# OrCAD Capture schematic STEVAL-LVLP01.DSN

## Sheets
1 01_Gate_Driver: size A4; title: B-DRIVE-LPLV01; rev: 1.0; company: STMicroelectronics; note: N/A; note: AMG ANALOG
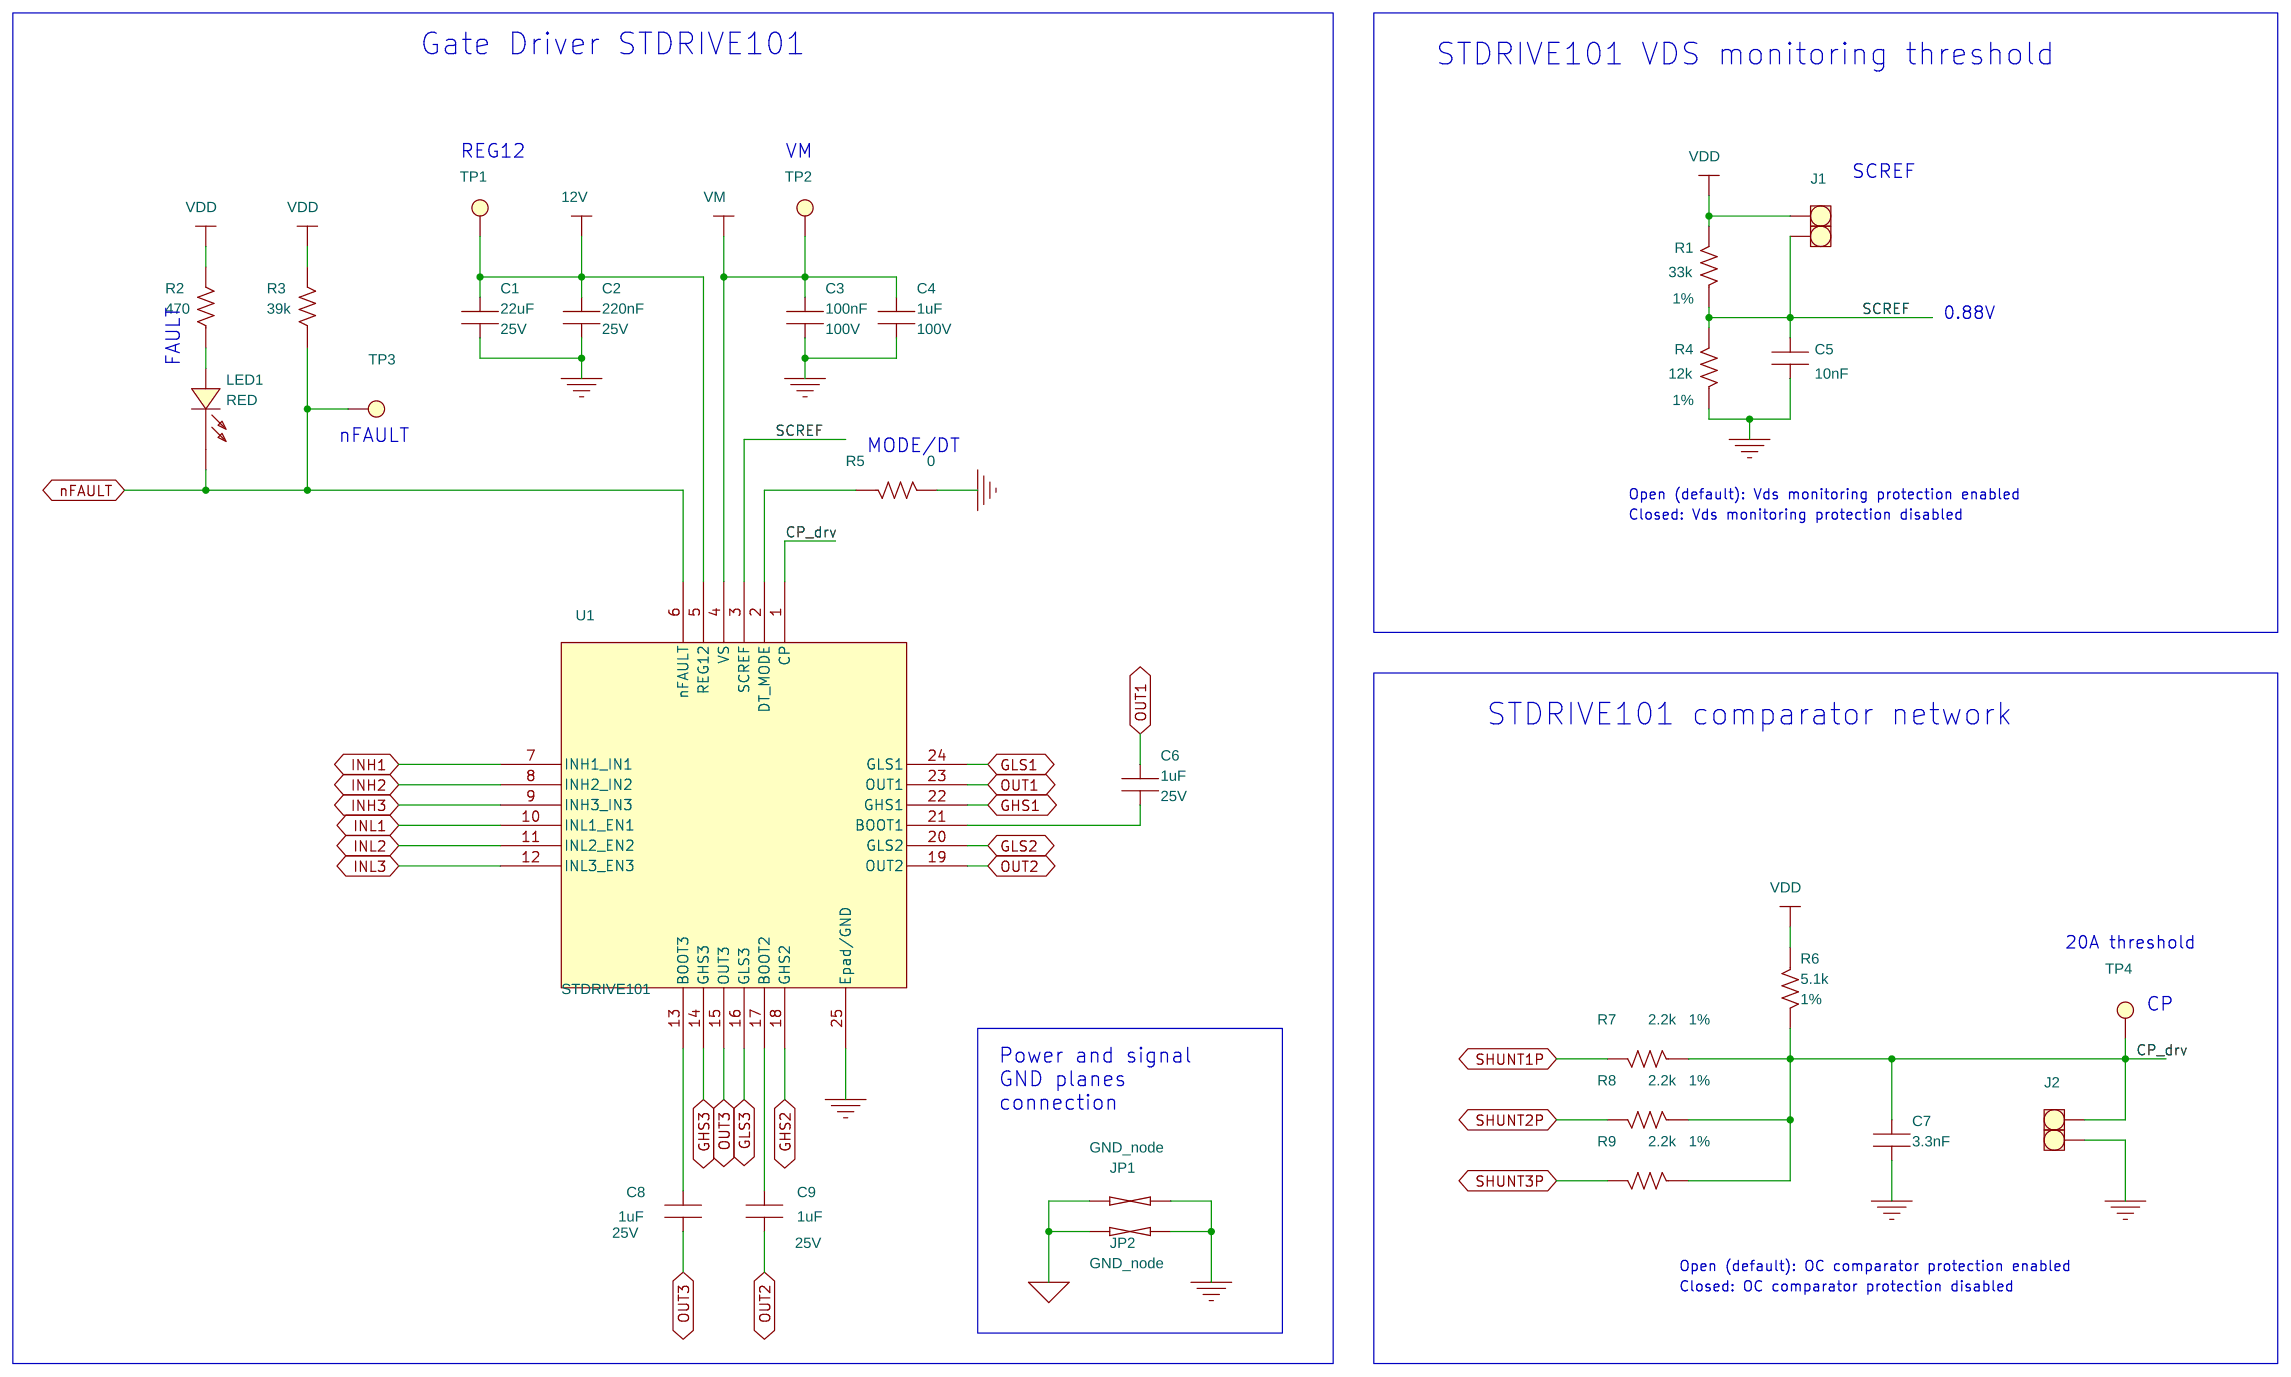
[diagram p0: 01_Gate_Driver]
2 02_Power_stage: size A4
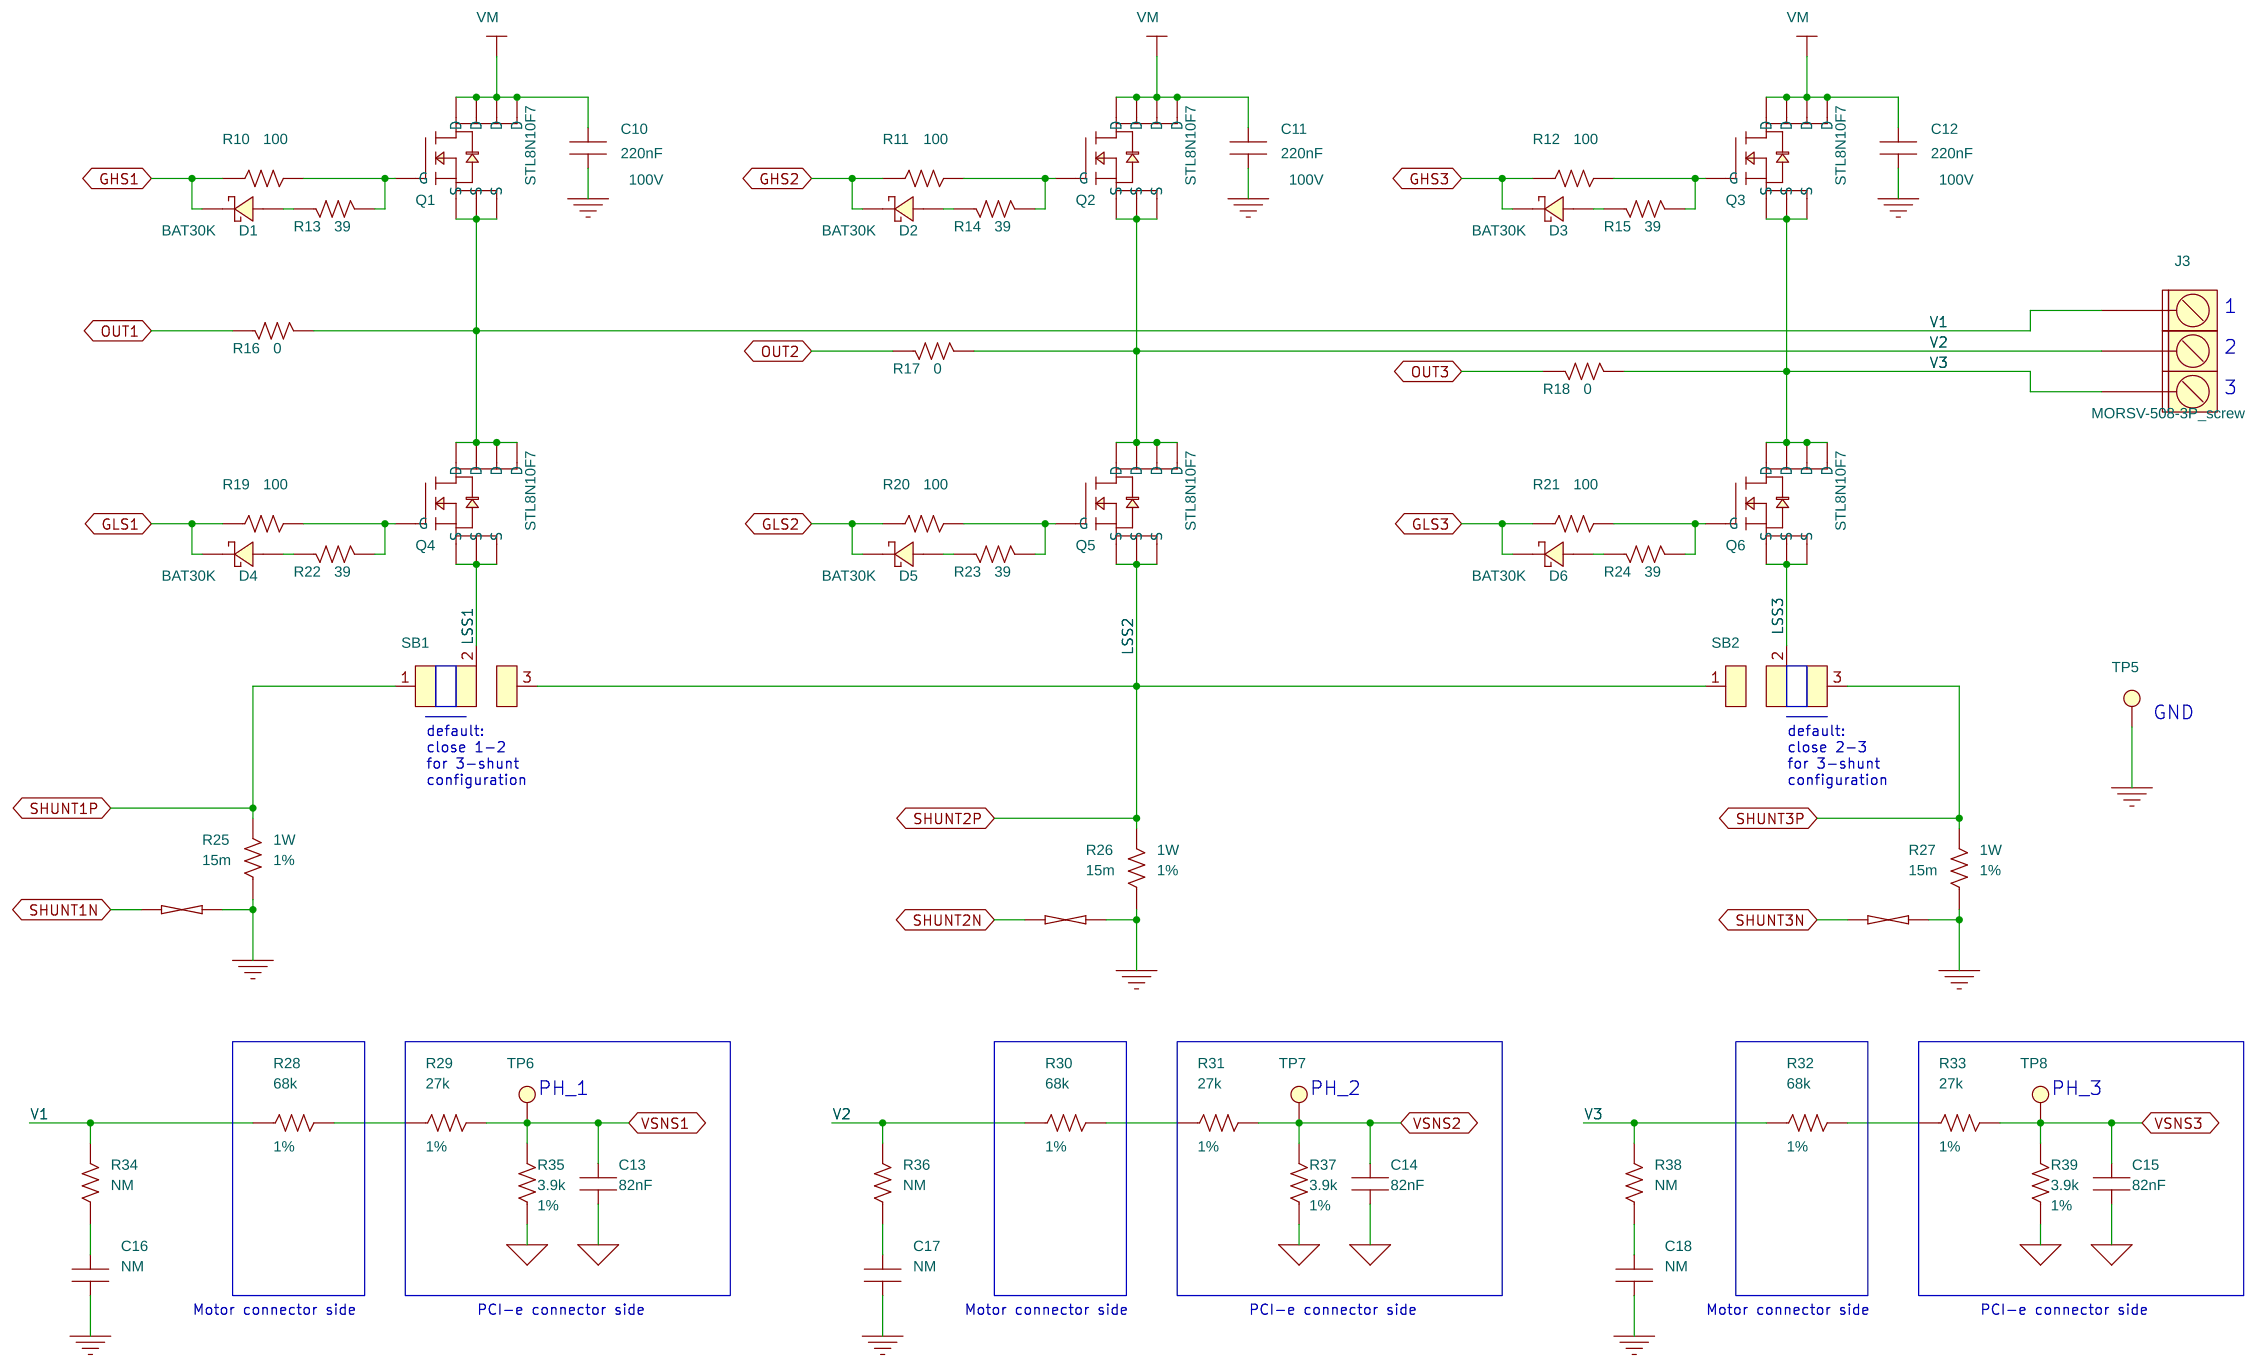
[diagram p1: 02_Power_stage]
3 03_Current_sens: size A4
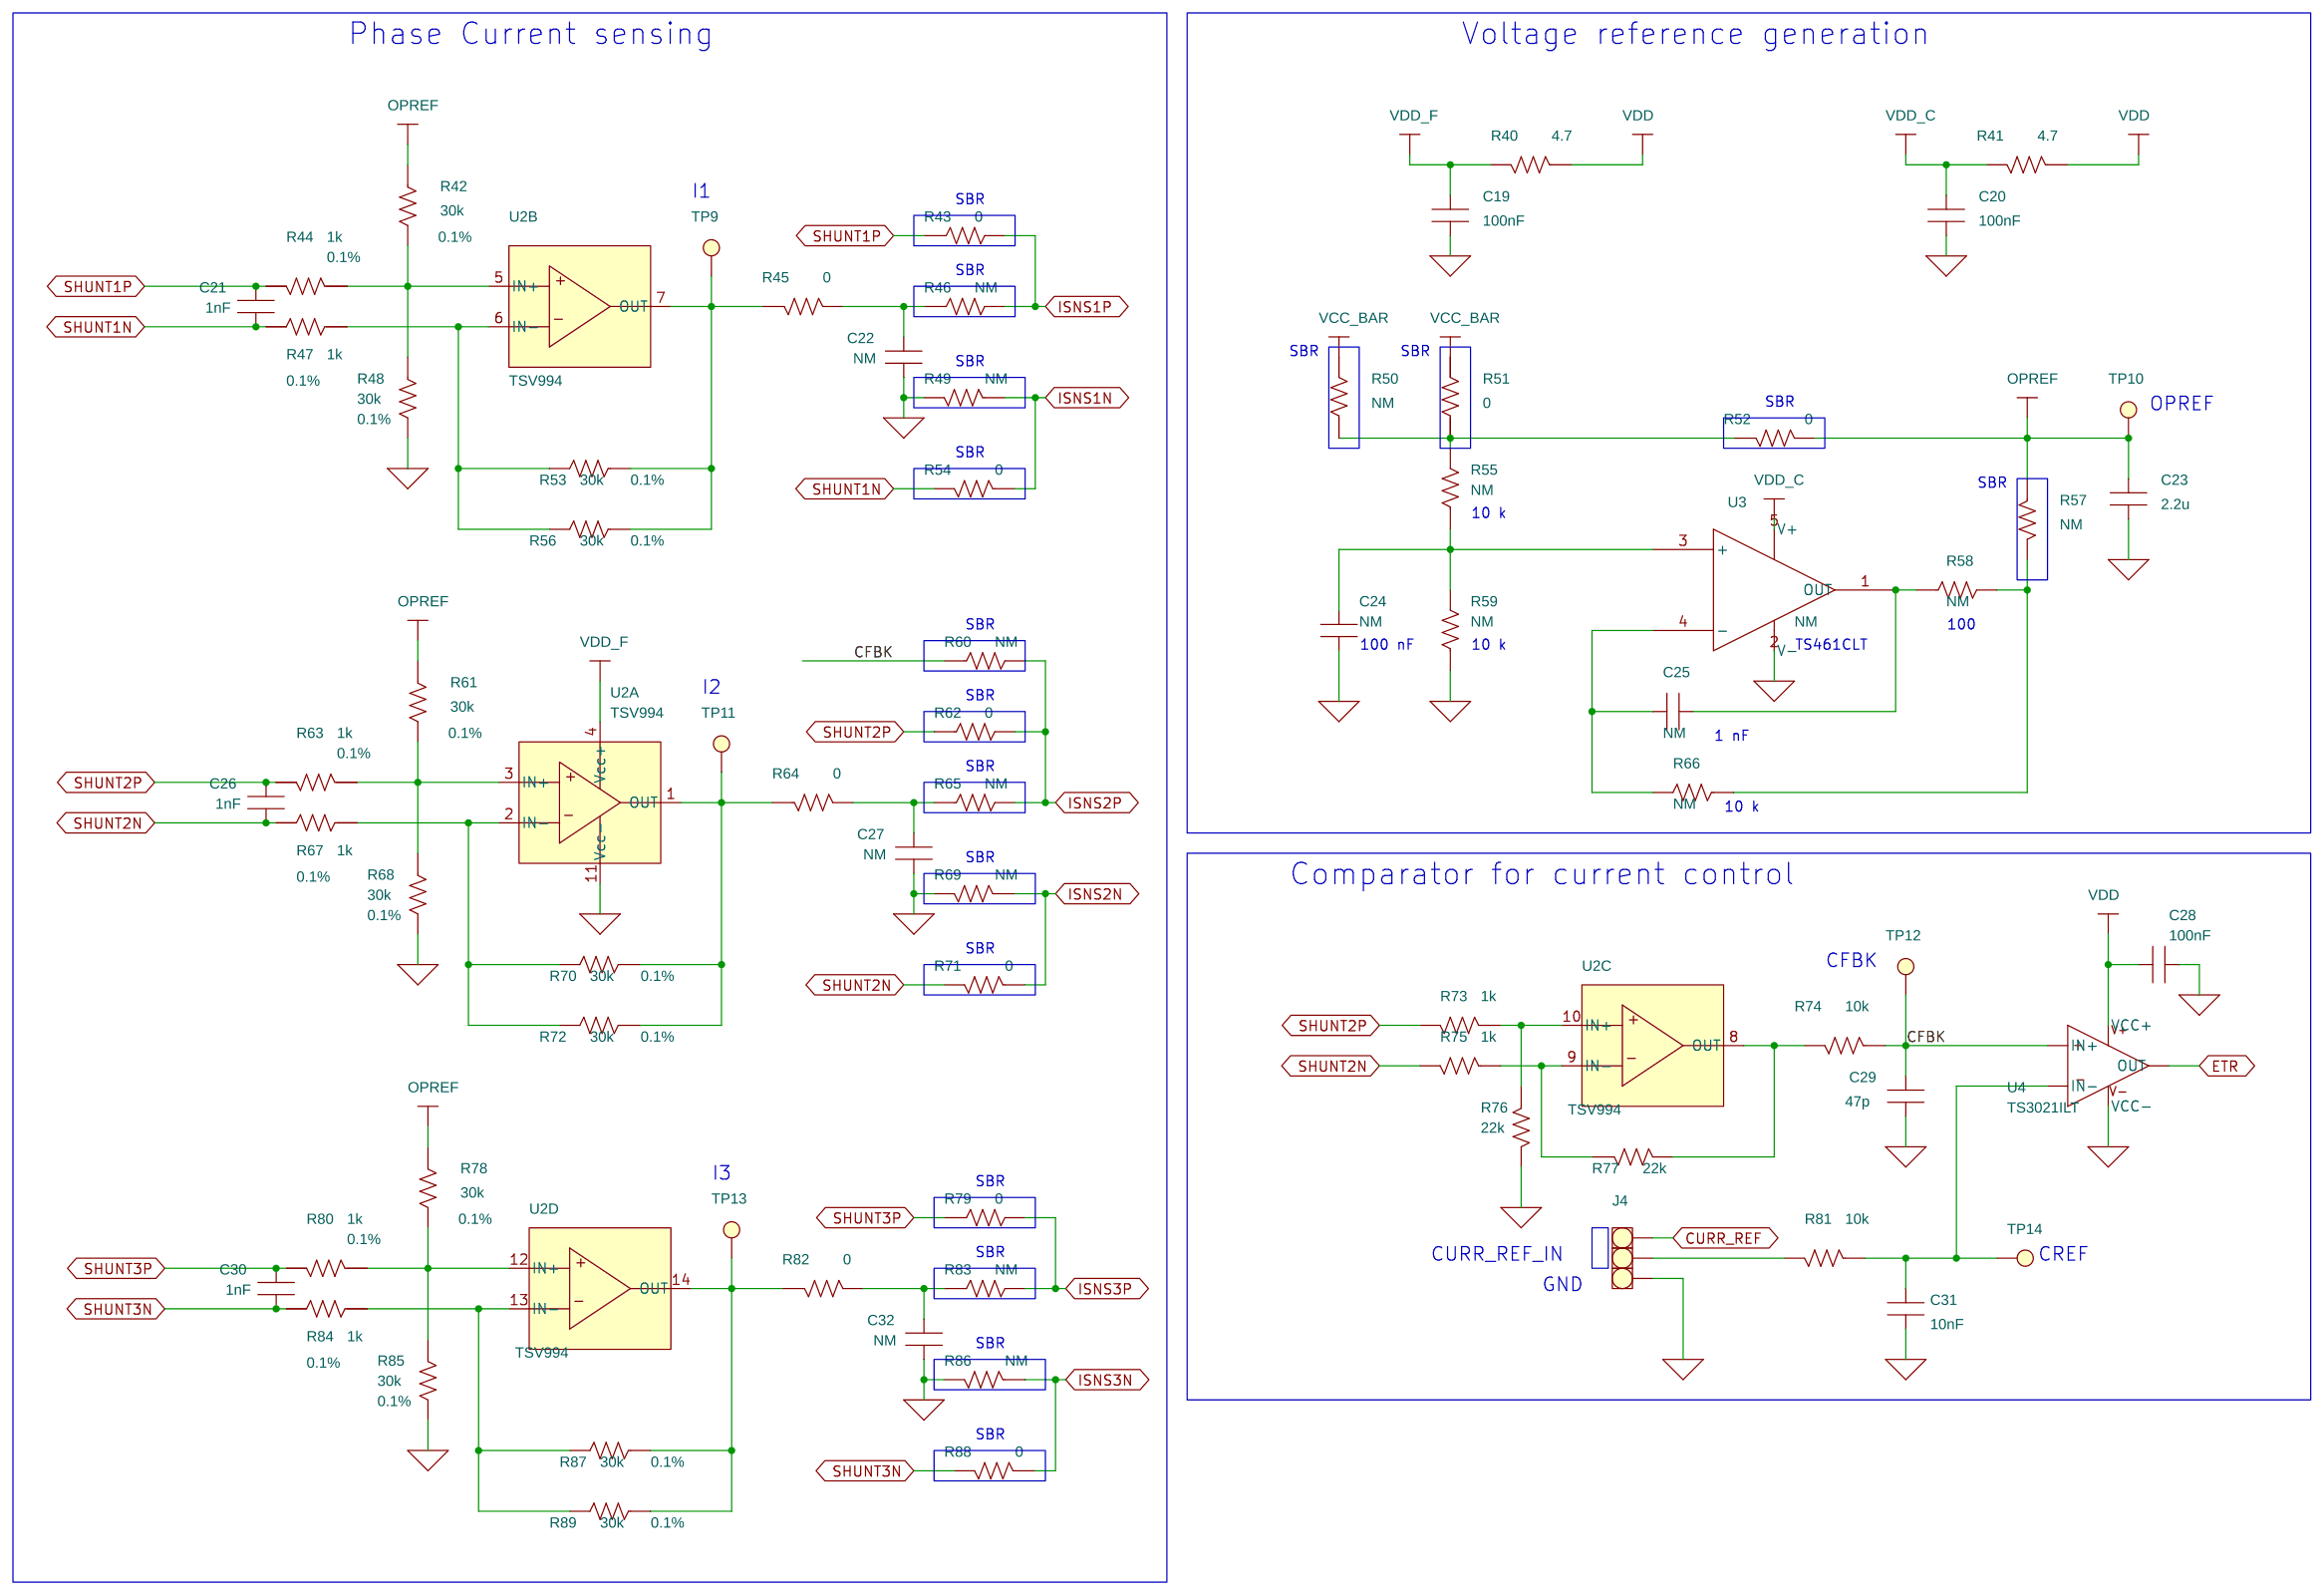
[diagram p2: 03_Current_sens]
4 04_Buck_Converter: size A4
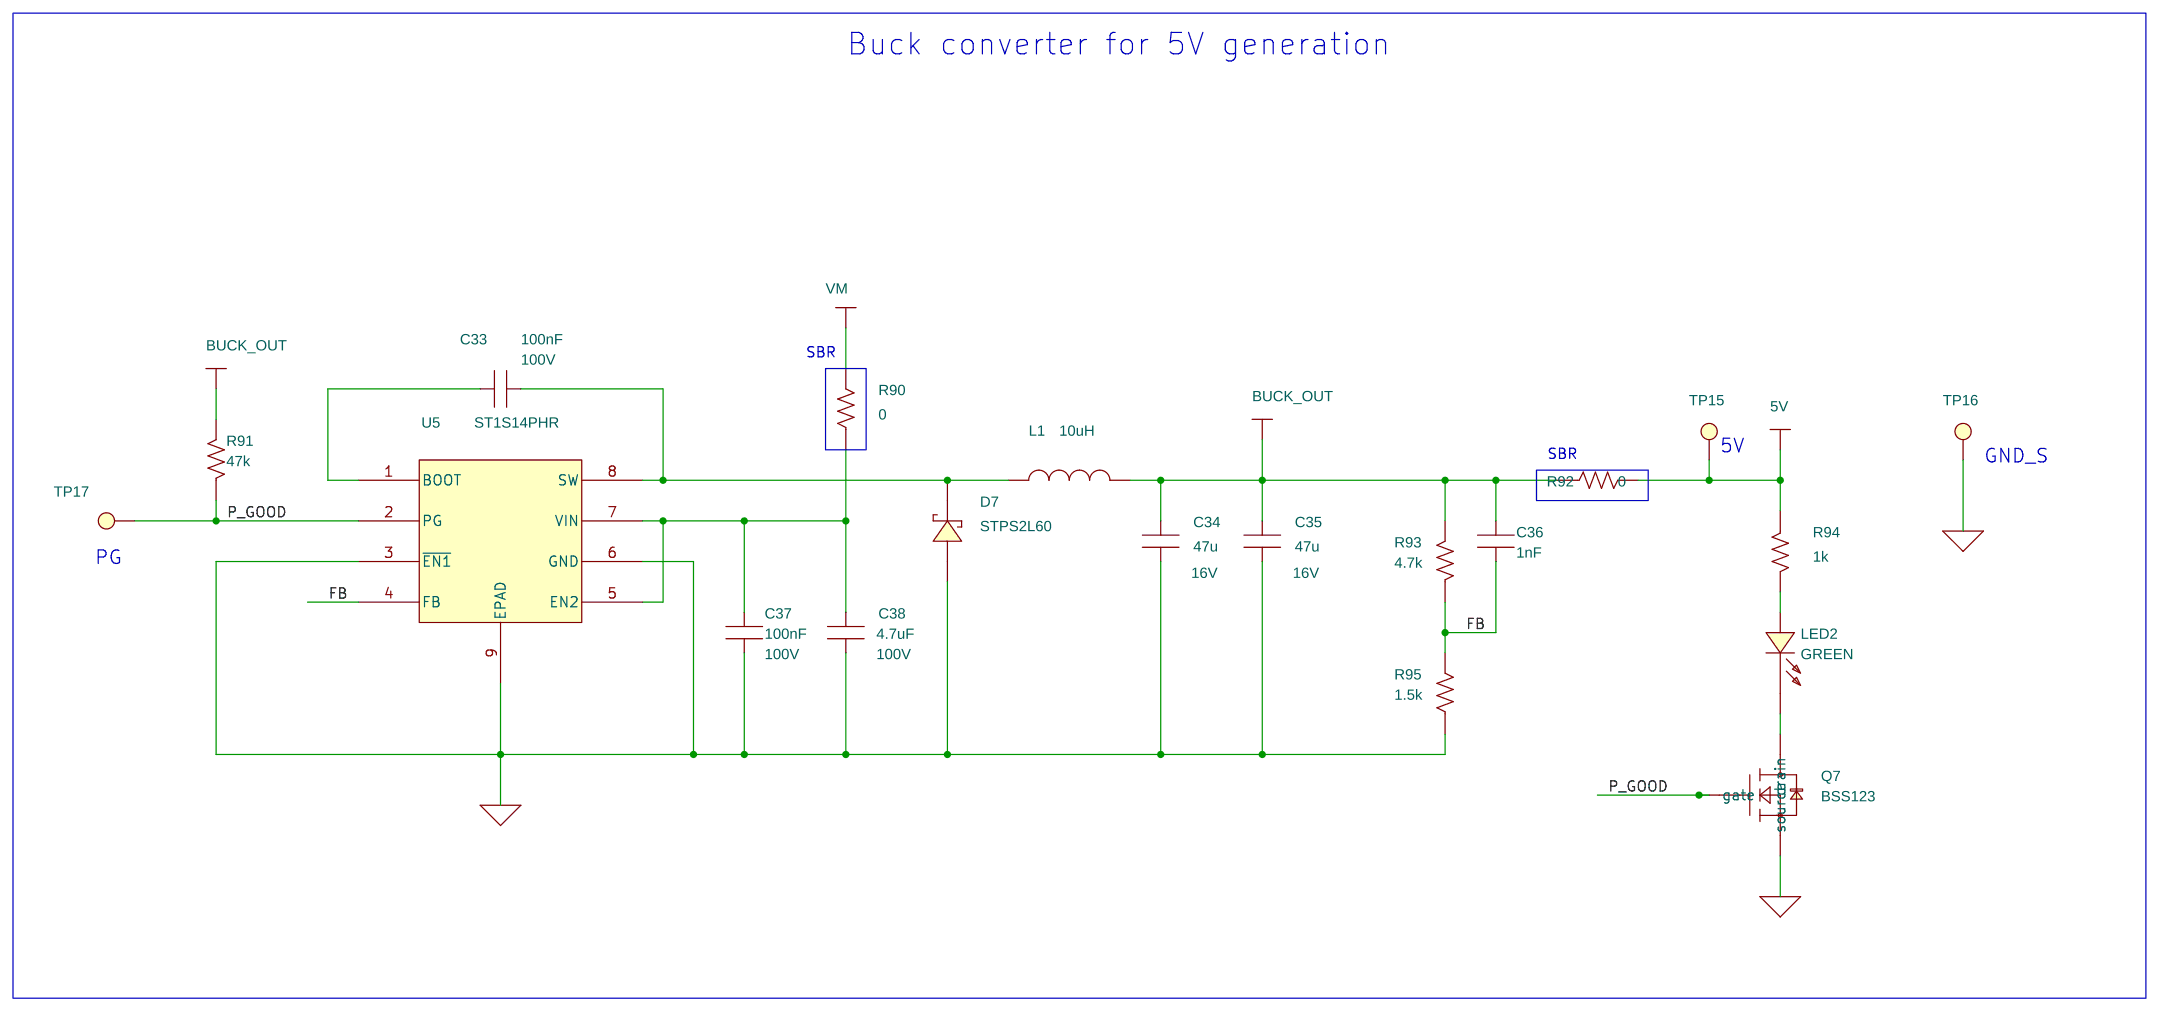
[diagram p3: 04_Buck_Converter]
5 05_Misc_Connectors: size A4
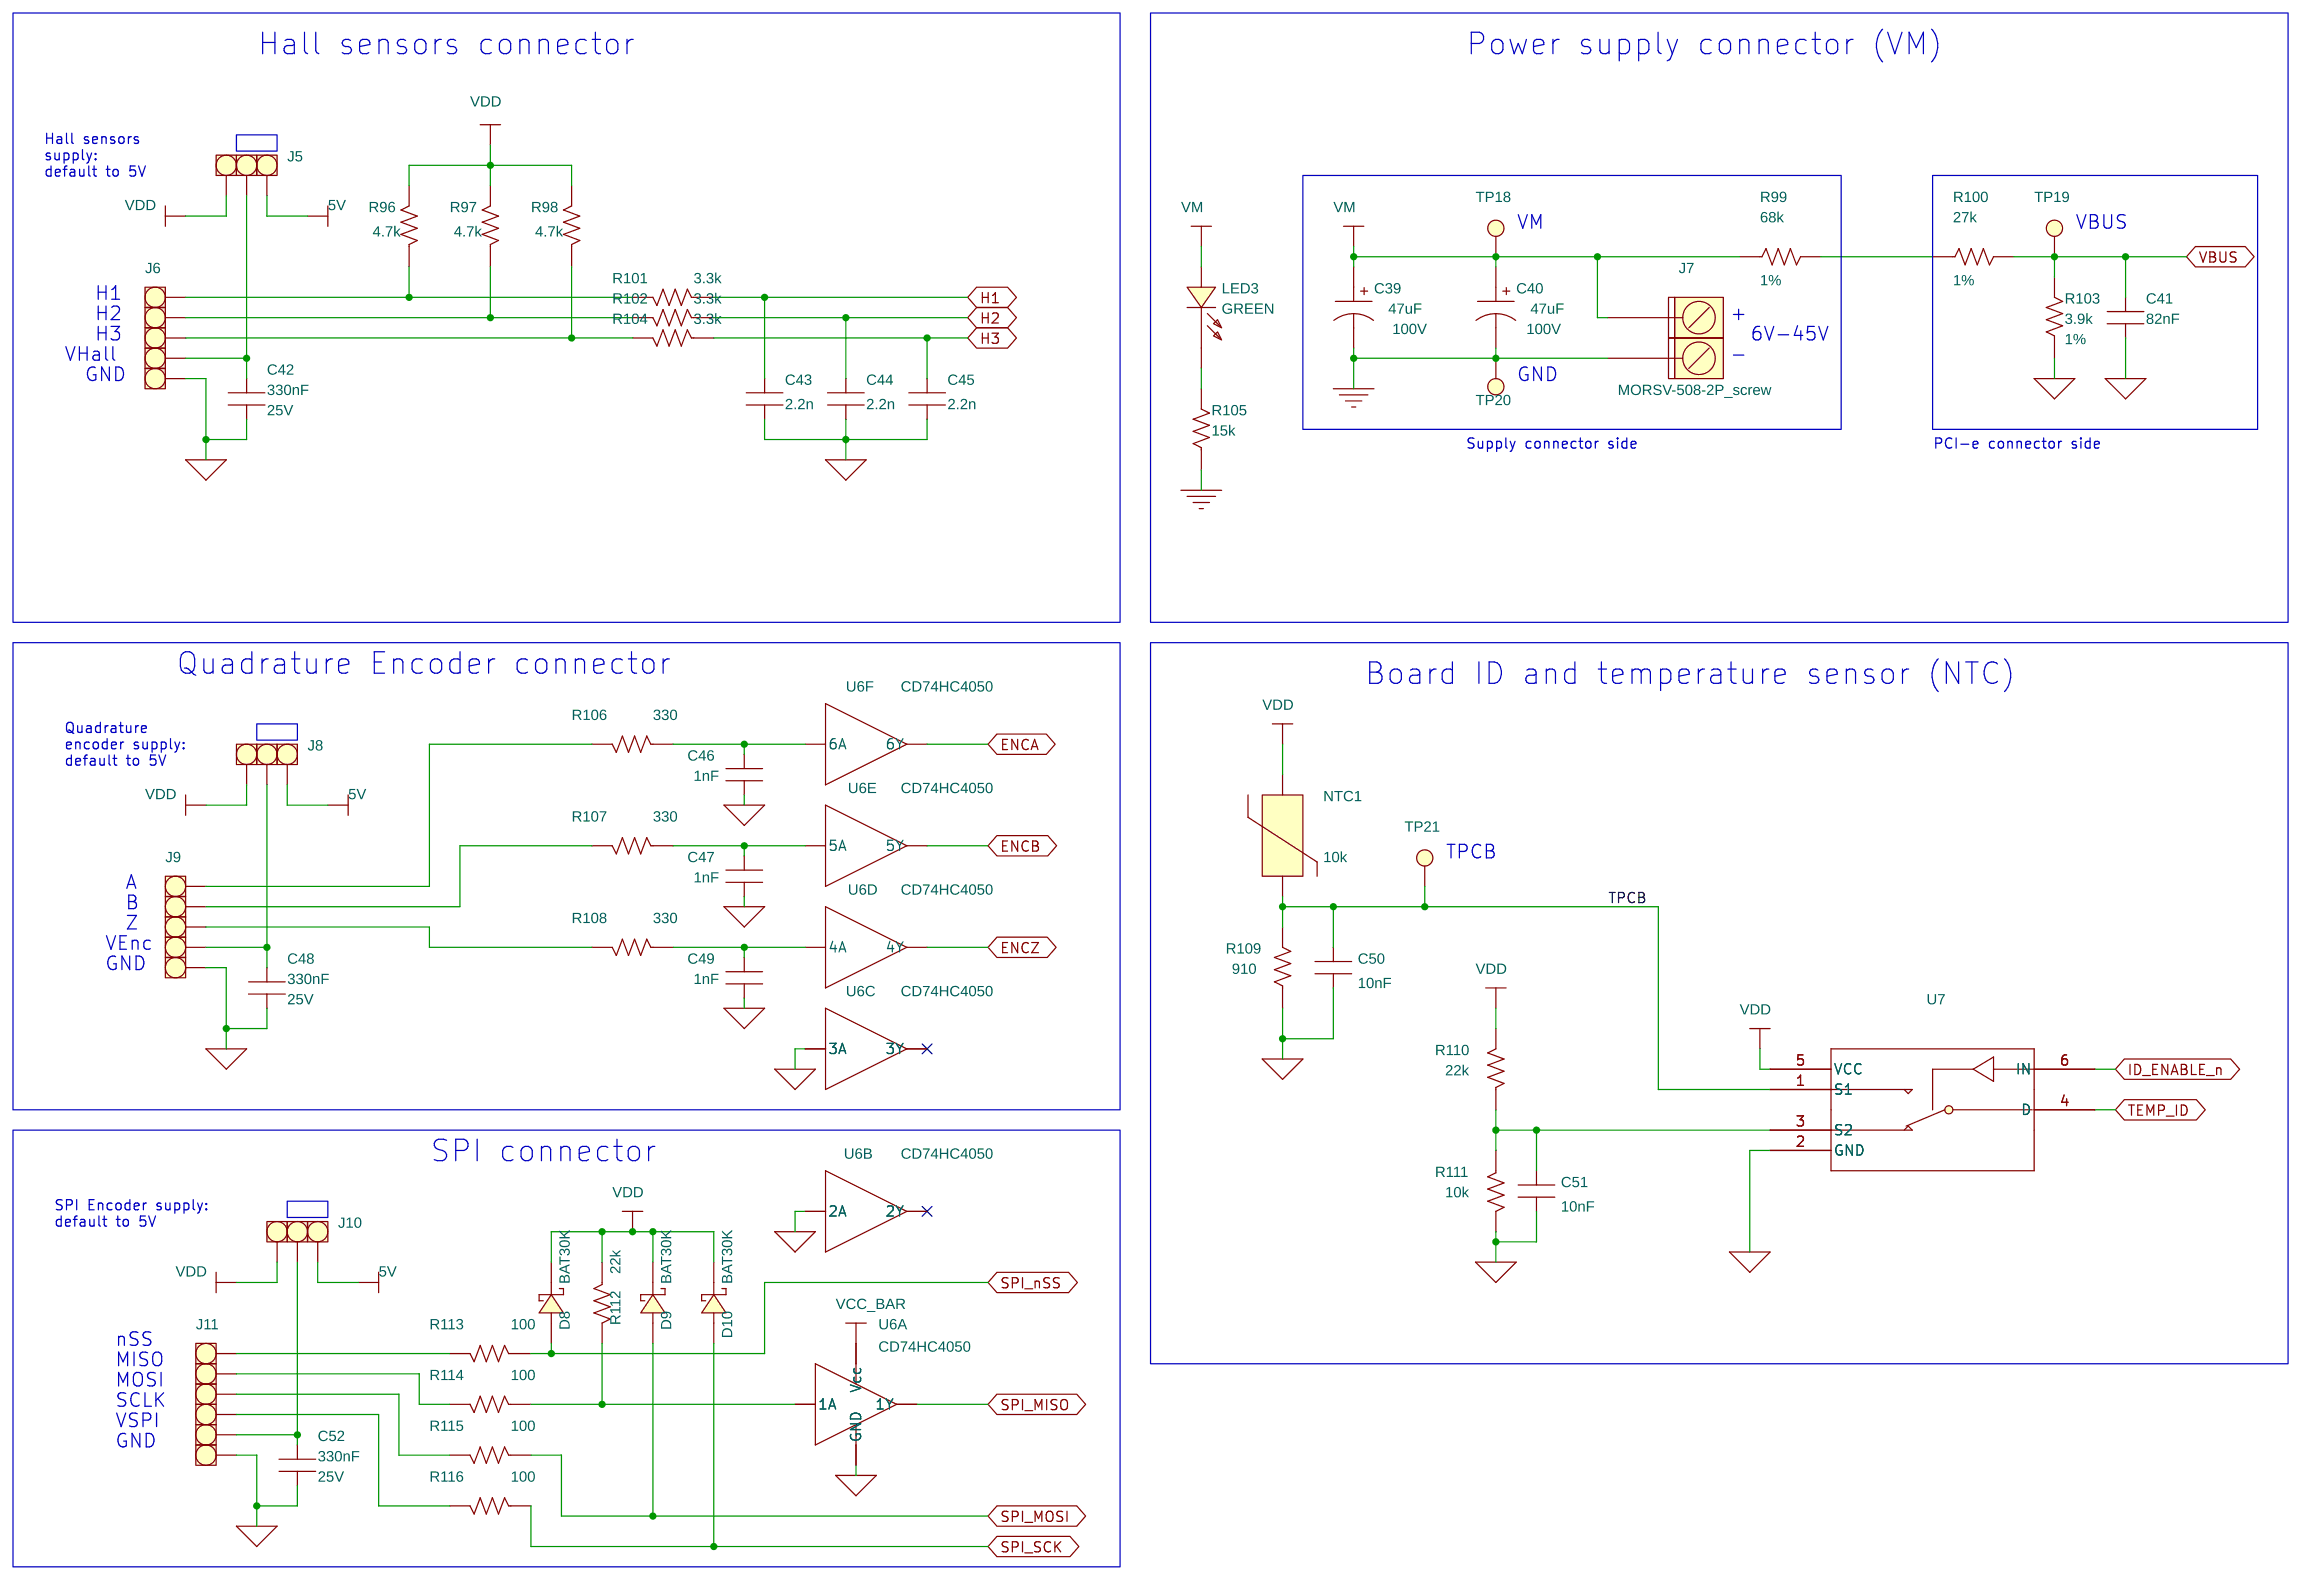
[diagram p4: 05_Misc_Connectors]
6 06_MC_Connector_V2: size A4
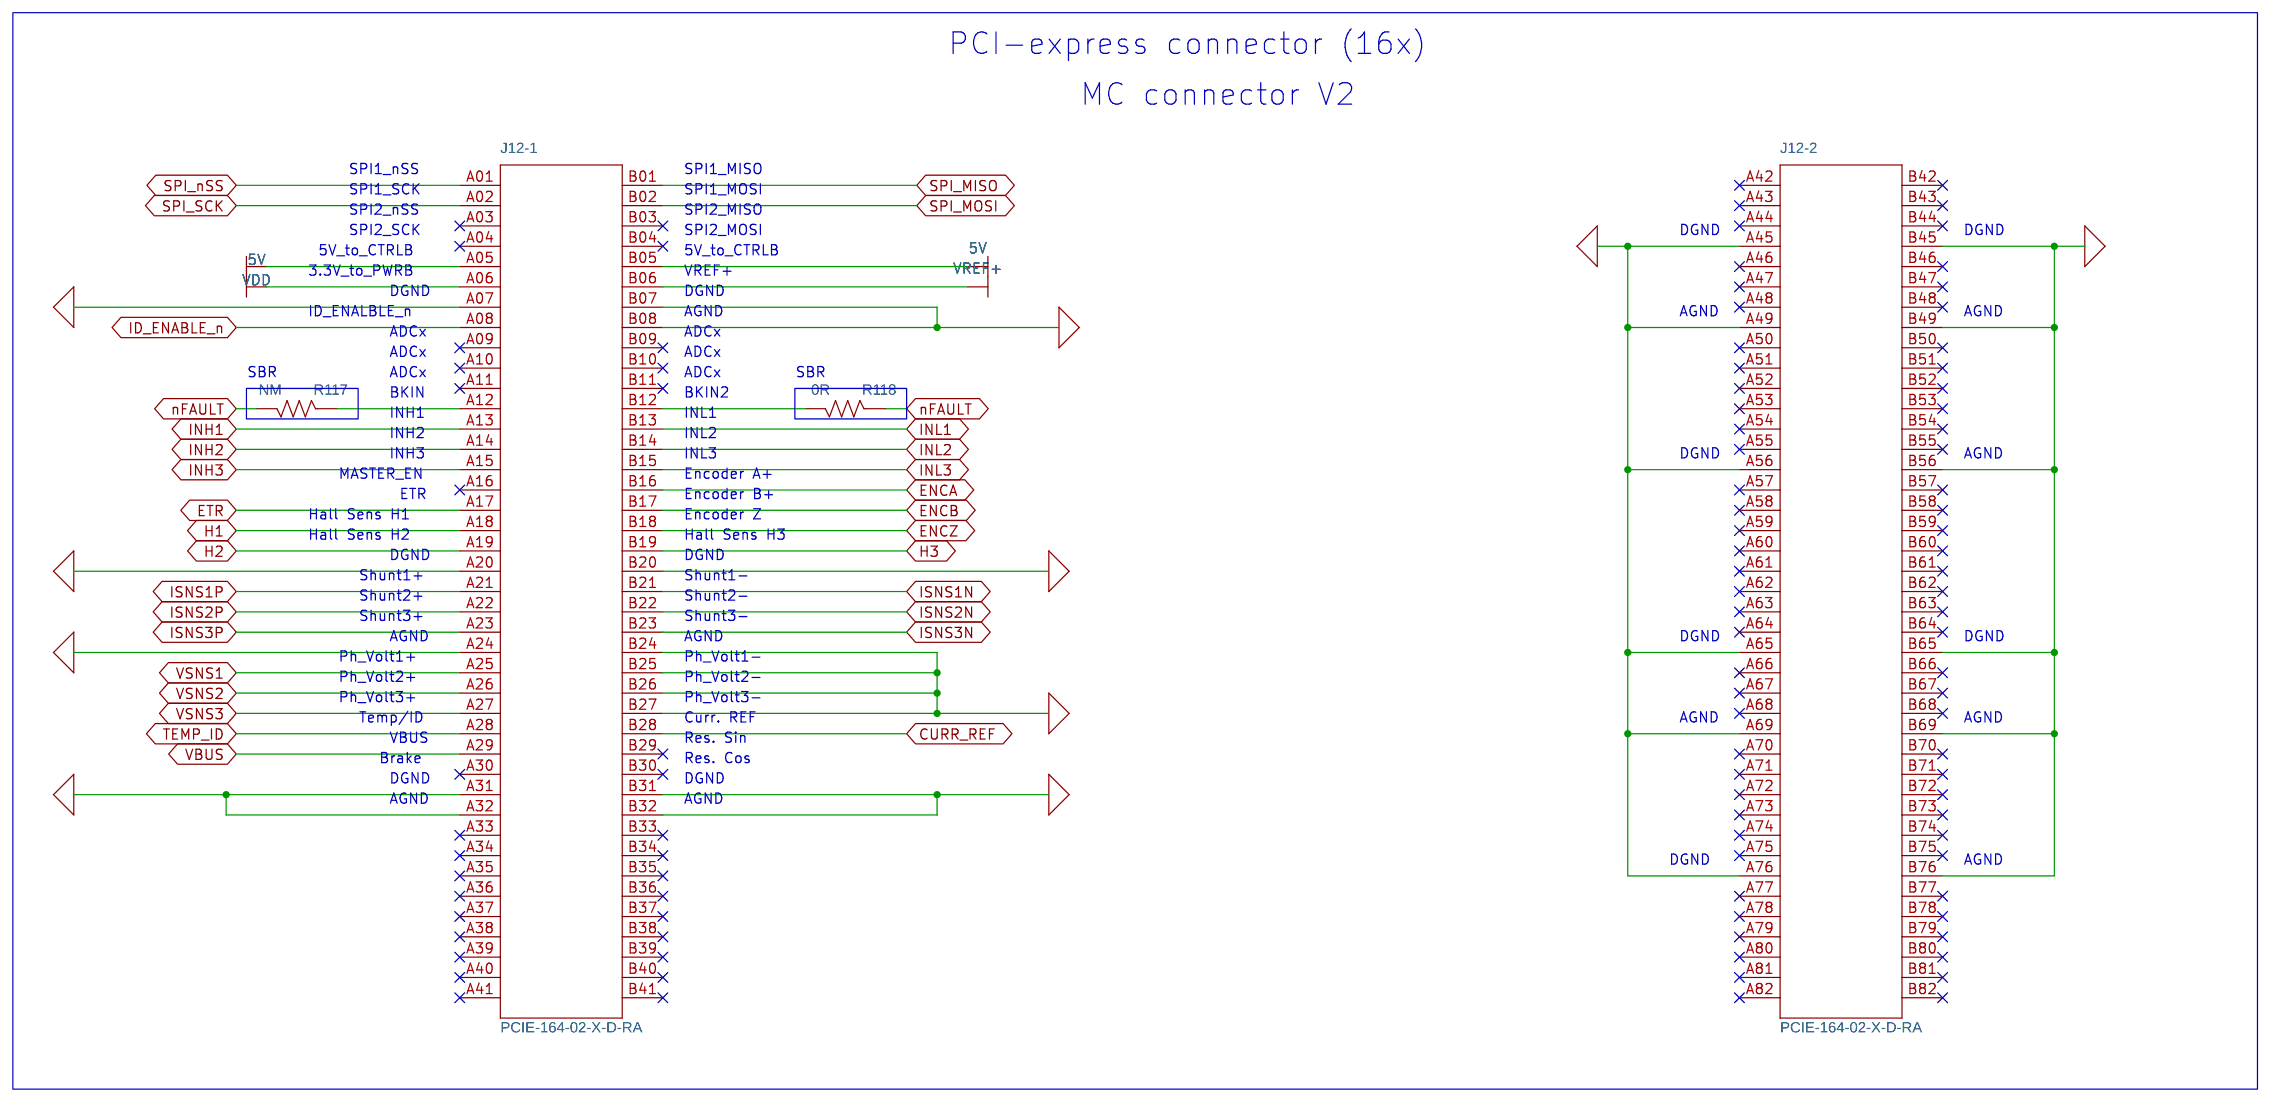
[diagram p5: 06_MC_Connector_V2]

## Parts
sheet 01_Gate_Driver
C1  22uF  [C1210]
C2  220nF  [C0603]
C3  100nF  [C0805]
C4  1uF  [C0805]
C5  10nF  [C0603]
C6  1uF  [C0805]
C7  3.3nF  [C0603]
C8  1uF  [C0805]
C9  1uF  [C0805]
J1  STRIP 1x2  [STRIP254P-M-2]
J2  STRIP 1x2  [STRIP254P-M-2]
JP1  GND_node  [cortonosolder200mils]
JP2  GND_node  [cortonosolder200mils]
LED1  RED  [led-0805]
R1  33k  [R0603]
R2  470  [R0603]
R3  39k  [R0603]
R4  12k  [R0603]
R5  0  [R0603]
R6  5.1k  [R0603]
R7  2.2k  [R0603]
R8  2.2k  [R0603]
R9  2.2k  [R0603]
TP1  TP-SMD-S1751-46R  [S1751-46R]
TP2  TP-SMD-S1751-46R  [S1751-46R]
TP3  TP-SMD-S1751-46R  [S1751-46R]
TP4  TP-SMD-S1751-46R  [S1751-46R]
U1  STDRIVE101  [QFN24-4X4]
sheet 02_Power_stage
C10  220nF  [C1206]
C11  220nF  [C1206]
C12  220nF  [C1206]
C13  82nF  [C0603]
C14  82nF  [C0603]
C15  82nF  [C0603]
C16  NM  [C0603]
C17  NM  [C0603]
C18  NM  [C0603]
D1  BAT30K  [SOD523]
D2  BAT30K  [SOD523]
D3  BAT30K  [SOD523]
D4  BAT30K  [SOD523]
D5  BAT30K  [SOD523]
D6  BAT30K  [SOD523]
J3  MORSV-508-3P_screw  [MORSV-508-3P]
JP3  CurrentSense  [CurrentSense-12]
JP4  CurrentSense  [CurrentSense-12]
JP5  CurrentSense  [CurrentSense-12]
Q1  STL8N10F7  [PFLAT_3_3X3_3]
Q2  STL8N10F7  [PFLAT_3_3X3_3]
Q3  STL8N10F7  [PFLAT_3_3X3_3]
Q4  STL8N10F7  [PFLAT_3_3X3_3]
Q5  STL8N10F7  [PFLAT_3_3X3_3]
Q6  STL8N10F7  [PFLAT_3_3X3_3]
R10  100  [R0603]
R11  100  [R0603]
R12  100  [R0603]
R13  39  [R0603]
R14  39  [R0603]
R15  39  [R0603]
R16  0  [R0603]
R17  0  [R0603]
R18  0  [R0603]
R19  100  [R0603]
R20  100  [R0603]
R21  100  [R0603]
R22  39  [R0603]
R23  39  [R0603]
R24  39  [R0603]
R25  15m  [R2512]
R26  15m  [R2512]
R27  15m  [R2512]
R28  68k  [R0603]
R29  27k  [R0603]
R30  68k  [R0603]
R31  27k  [R0603]
R32  68k  [R0603]
R33  27k  [R0603]
R34  NM  [R0603]
R35  3.9k  [R0603]
R36  NM  [R0603]
R37  3.9k  [R0603]
R38  NM  [R0603]
R39  3.9k  [R0603]
SB1  Power_Solder_Bridge  [254-PITCH_HEADER-2X3-JUMP]
SB2  Power_Solder_Bridge  [254-PITCH_HEADER-2X3-JUMP]
TP5  TP-SMD-S1751-46R  [S1751-46R]
TP6  TP-SMD-S1751-46R  [S1751-46R]
TP7  TP-SMD-S1751-46R  [S1751-46R]
TP8  TP-SMD-S1751-46R  [S1751-46R]
sheet 03_Current_sens
C19  100nF  [C0603]
C20  100nF  [C0603]
C21  1nF  [C0603]
C22  NM  [C0603]
C23  2.2u  [C0603]
C24  NM  [C0603]
C25  NM  [C0603]
C26  1nF  [C0603]
C27  NM  [C0603]
C28  100nF  [C0603]
C29  47p  [C0603]
C30  1nF  [C0603]
C31  10nF  [C0603]
C32  NM  [C0603]
J4  STRIP 1x3  [STRIP254P-M-3]
R40  4.7  [R0603]
R41  4.7  [R0603]
R42  30k  [R0603]
R43  0  [J0603]
R44  1k  [R0603]
R45  0  [R0603]
R46  NM  [J0603]
R47  1k  [R0603]
R48  30k  [R0603]
R49  NM  [J0603]
R50  NM  [J0603]
R51  0  [J0603]
R52  0  [R0603]
R53  30k  [R0603]
R54  0  [J0603]
R55  NM  [R0603]
R56  30k  [R0603]
R57  NM  [J0603]
R58  NM  [R0603]
R59  NM  [R0603]
R60  NM  [J0603]
R61  30k  [R0603]
R62  0  [J0603]
R63  1k  [R0603]
R64  0  [R0603]
R65  NM  [J0603]
R66  NM  [R0603]
R67  1k  [R0603]
R68  30k  [R0603]
R69  NM  [J0603]
R70  30k  [R0603]
R71  0  [J0603]
R72  30k  [R0603]
R73  1k  [R0603]
R74  10k  [R0603]
R75  1k  [R0603]
R76  22k  [R0603]
R77  22k  [R0603]
R78  30k  [R0603]
R79  0  [J0603]
R80  1k  [R0603]
R81  10k  [R0603]
R82  0  [R0603]
R83  NM  [J0603]
R84  1k  [R0603]
R85  30k  [R0603]
R86  NM  [J0603]
R87  30k  [R0603]
R88  0  [J0603]
R89  30k  [R0603]
TP9  TP-SMD-S1751-46R  [S1751-46R]
TP10  TP-SMD-S1751-46R  [S1751-46R]
TP11  TP-SMD-S1751-46R  [S1751-46R]
TP12  TP-SMD-S1751-46R  [S1751-46R]
TP13  TP-SMD-S1751-46R  [S1751-46R]
TP14  TP-SMD-S1751-46R  [S1751-46R]
U2  TSV994  [tssop14]  (sections A,B,C,D)
U3  NM  [SOT23-5L]
U4  TS3021ILT  [SOT23-5L]
sheet 04_Buck_Converter
C33  100nF  [C0805]
C34  47u  [C1210]
C35  47u  [C1210]
C36  1nF  [C0603]
C37  100nF  [C0805]
C38  4.7uF  [C1210]
D7  STPS2L60  [SMA]
L1  10uH  [CLF7045NI-D-TDK]
LED2  GREEN  [led-0603]
Q7  BSS123  [SOT23]
R90  0  [J0805]
R91  47k  [R0603]
R92  0  [J0805]
R93  4.7k  [R0603]
R94  1k  [R0603]
R95  1.5k  [R0603]
TP15  TP-SMD-S1751-46R  [S1751-46R]
TP16  TP-SMD-S1751-46R  [S1751-46R]
TP17  TP-SMD-S1751-46R  [S1751-46R]
U5  ST1S14PHR  [so8-ep-9]
sheet 05_Misc_Connectors
C39  47uF  [C-POL12_5X13_5]
C40  47uF  [C-POL12_5X13_5]
C41  82nF  [C0603]
C42  330nF  [C0603]
C43  2.2n  [C0603]
C44  2.2n  [C0603]
C45  2.2n  [C0603]
C46  1nF  [C0603]
C47  1nF  [C0603]
C48  330nF  [C0603]
C49  1nF  [C0603]
C50  10nF  [C0603]
C51  10nF  [C0603]
C52  330nF  [C0603]
D8  BAT30K  [SOD523]
D9  BAT30K  [SOD523]
D10  BAT30K  [SOD523]
J5  STRIP 1x3  [STRIP254P-M-3]
J6  STRIP 1x5  [STRIP254P-M-5]
J7  MORSV-508-2P_screw  [MORSV-508-2P]
J8  STRIP 1x3  [STRIP254P-M-3]
J9  STRIP 1x5  [STRIP254P-M-5]
J10  STRIP 1x3  [STRIP254P-M-3]
J11  STRIP 1x6  [STRIP254P-M-6]
LED3  GREEN  [led-0603]
NTC1  10k  [R0603]
R96  4.7k  [R0603]
R97  4.7k  [R0603]
R98  4.7k  [R0603]
R99  68k  [R0603]
R100  27k  [R0603]
R101  3.3k  [R0603]
R102  3.3k  [R0603]
R103  3.9k  [R0603]
R104  3.3k  [R0603]
R105  15k  [R0603]
R106  330  [R0603]
R107  330  [R0603]
R108  330  [R0603]
R109  910  [R0603]
R110  22k  [R0603]
R111  10k  [R0603]
R112  22k  [R0603]
R113  100  [R0603]
R114  100  [R0603]
R115  100  [R0603]
R116  100  [R0603]
TP18  TP-SMD-S1751-46R  [S1751-46R]
TP19  TP-SMD-S1751-46R  [S1751-46R]
TP20  TP-SMD-S1751-46R  [S1751-46R]
TP21  TP-SMD-S1751-46R  [S1751-46R]
U6  CD74HC4050  [TSSOP16]  (sections A,B,C,D,E,F)
U7  STG3157CTR  [sot323-6L]
sheet 06_MC_Connector_V2
J12  PCIE-164-02-X-D-RA  [SAMTEC_PCIE-164-02-X-D-RA]  (sections -1,-2)
R117  NM  [J0603]
R118  0R  [J0603]

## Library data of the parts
C1 = C-1210: Distributor: RS; Distributor Part Number: 103-4210; IFARCAD Footprint: CAPC-1210; Manufacturer: Taiyo Yuden; Part Number: TMK325B7226KM-PR; TOLERANCE: 10%; VOLTAGE: 25V
C2 = C-0603: IFARCAD Footprint: CAPC-0603; TOLERANCE: 10%; VOLTAGE: 25V
C3 C33 C37 = C-0805: Distributor: RS; Distributor Part Number: 802-9951; IFARCAD Footprint: CAPC-0805; Manufacturer: Kemet; Part Number: C0805C104K1RACTU; TOLERANCE: 10%; VOLTAGE: 100V
C4 = C-1206: IFARCAD Footprint: CAPC-0805; Manufacturer: TDK; Package: Size 0805; Part Number: CGA4J3X7S2A105K125AE; TOLERANCE: 10%; VOLTAGE: 100V
C5 C31 C50 C51 = C-0603: IFARCAD Footprint: CAPC-0603; Manufacturer: Murata; Package: Size 0603; Part Number: GCM188R72A103KA37D; TOLERANCE: 10%; VOLTAGE: 25V
C6 C8 C9 = C-0805: IFARCAD Footprint: CAPC-0805; Manufacturer: Kemet; Part Number: C0805C105K3RACTU; TOLERANCE: 10%; VOLTAGE: 25V
C7 = C-0603: IFARCAD Footprint: CAPC-0603; Manufacturer: Murata; Package: Size 0603; TOLERANCE: 10%; VOLTAGE: 16V
J1 J2 = STRIP_1x2
JP1-JP5 = CurrentSense: IFARCAD Footprint: SHORTPIN-20MIL_IN2
LED1 = LED-0805: IFARCAD Footprint: LEDC-0805; Manufacturer: Wurth Elektronik; Package: Size 0805; Part Number: 150080RS75000
R1-R4 R6-R9 = R-0603: IFARCAD Footprint: RESC-0603; POWER: 1/10W; TOLERANCE: 1%; Watt: 1/10W
R5 R16-R18 R45 R52 R64 R82 = R-0603: Watt: 1/10 W
TP1-TP21 = TP-SMD-S1751-46R
U1 = STDRIVE101
C10-C12 = C-1206: VOLTAGE: 100V
C13-C15 C41 = C-0603: IFARCAD Footprint: CAPC-0603; Manufacturer: Murata; Package: Size 0603; TOLERANCE: 10%; VOLTAGE: 25V
C16-C18 = C-0603: VOLTAGE: 100V
D1-D6 D8-D10 = BAT30K
J3 = MORSV-508-3P_screw
Q1-Q6 = STL11N6F7: N-channel 100 V, 17 mO typ., 8 A STripFET™ F7 Power MOSFET; ID: 8 A; Vdss: 100V
R10-R15 R19-R24 R113-R116 = R-0603: Watt: 1/4 W
R25-R27 = R-2512: Distributor: RS; Distributor Part Number: 794-4339; Manufacturer: Bourns; Part Number: CRF2512-FZ-R015ELF; TOLERANCE: 1%; Watt: 1W
R28-R33 R35 R37 R39 R99 R100 R103 = R-0603: TOLERANCE: 1%; Watt: 1/10 W
R34 R36 R38 = R-0603: TOLERANCE: 1%; Watt: 1/4 W
SB1 SB2 = Power_Solder_Bridge
C19 C20 C28 = C-0603: Part Number: C0603C104K3RACTU; TOLERANCE: 10%; VOLTAGE: 25V
C21 C22 C24-C27 C29 C30 C32 C36 C46 C47 C49 = C-0603: TOLERANCE: 10%; VOLTAGE: 25V
C23 = C-0603: TOLERANCE: 10%; VOLTAGE: 16V
J4 J5 J8 J10 = STRIP_1x3
R40 R41 = R-0603
R42 R48 R53 R56 R61 R68 R70 R72 R78 R85 R87 R89 = R-0603: Distributor: RS; Distributor Part Number: 199-1422; Manufacturer: Yageo; Part Number: RT0603BRD0715KL; TOLERANCE: 0.1%
R43 R46 R49-R51 R54 R57 R60 R62 R65 R69 R71 R79 R83 R86 R88 R117 R118 = JUMPER-R0603
R44 R47 R63 R67 R80 R84 = R-0603: Manufacturer: Yageo; Part Number: RT0603BRE071KL; TOLERANCE: 0.1%
R55 R59 R66 = R-0603: Manufacturer: Yageo; Part Number: RT0603BRB0710KL; TOLERANCE: 0.1%
R58 = R-0603: TOLERANCE: <TOLERANCE>
R73-R77 R81 R94 R111 = R-0603: TOLERANCE: 1%
U2 = TSV994IPT: Distributor: Mouser; Distributor Part Number: 511-TSV994AIPT; Package: TSSOP-14; Part Number: TSV994AIPT
U3 = TS461CLT: Rail-to-rail input/output 12 MHz GBP operational amplifiers; Distributor: Mouser; Distributor Part Number: 511-TS461CL; Manufacturer: STMicroelectronics; Package: SOT23-5
U4 = TS3021ILT
C34 C35 = C-1210: Distributor: RS; Distributor Part Number: 846-7369; Manufacturer: Murata; Part Number: GRM32EC81C476KE15L; VOLTAGE: 16V
C38 = C-1210: Distributor: RS; Distributor Part Number: 181-9969; Manufacturer: AVX; Part Number: 12101C475KAT2A; TOLERANCE: 10%; VOLTAGE: 100V
D7 = STPS2L30A: Part Number: STPS2L60A or equivalent; Voltage: 60V
L1 = INDUCTOR: Wound Ferrite inductor; CURRENT: 3.0A; Manufacturer: TDK; Package: 7.4mm x 7mm x 4.5mm; Part Number: CLF7045NIT-100M-D; TOLERANCE: 20%
LED2 LED3 = LED-0603-GREEN-WE
Q7 = BSS123
R90 R92 = JUMPER-R0805
R91 R95 R106-R110 R112 = R-0603: Watt: 1/10W
R93 R96-R98 R101 R102 R104 = R-0603: IFARCAD Footprint: RESC-0603; POWER: 1/10W; TOLERANCE: 1%
U5 = ST1S14PHR
C39 C40 = C_EL-DIAM10: Manufacturer: Panasonic; Package: SMD d12.5 x 13.5mm; Part Number: EEVFK2A470Q; TOLERANCE: 20%; VOLTAGE: 100V
C42 C48 C52 = C-0603: IFARCAD Footprint: CAPC-0603; Manufacturer: Kemet; Part Number: C0603C104K3RACTU; TOLERANCE: 10%; VOLTAGE: 25V
C43-C45 = C-0603: IFARCAD Footprint: CAPC-0603; Manufacturer: 06035C222KAZ2A; Part Number: AVX; TOLERANCE: 10%
J6 J9 = STRIP_1x5
J7 = MORSV-508-2P_screw_0
J11 = STRIP_1x6
NTC1 = NTC-NCP18XH103F03RB: Manufacturer: Vishay; Part Number: NTCS0603E3103FMT; TOLERANCE: 1%
R105 = R-0603: POWER: 1/2W; Watt: 1/4W
U6 = CD74HC4050PW
U7 = STG3157CTR
J12 = PCIE-164-02-X-D-RA

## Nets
5V: J5.1 J8.1 J10.1 J12.A05 J12.B05 R92.2 R94.1 TP15.1
12V: C1.2 C2.1 TP1.1 U1.5(REG12)
GND: C1.1 C2.2 C3.1 C4.1 C5.1 C7.1 C10.1 C11.1 C12.1 C16.1 C17.1 C18.1 C39.2(NEG) C40.2(NEG) J2.2 J7.2 JP1.2 JP2.2 JP3.1 JP4.1 JP5.1 R4.1 R5.2 R25.1 R26.1 R27.1 R105.1 TP5.1 TP20.1 U1.25(Epad/GND)
GND_SIGNAL: C13.1 C14.1 C15.1 C19.1 C20.1 C22.1 C23.2 C24.2 C27.1 C28.2 C29.1 C31.1 C32.1 C34.1 C35.1 C37.2 C38.1 C41.1 C42.2 C43.2 C44.2 C45.2 C46.1 C47.1 C48.2 C49.1 C50.1 C51.1 C52.2 D7.2 J4.3 J6.5 J9.5 J11.6 J12.A07 J12.A20 J12.A24 J12.A31 J12.A32 J12.A45 J12.A49 J12.A56 J12.A65 J12.A69 J12.A76 J12.B07 J12.B08 J12.B20 J12.B24 J12.B25 J12.B26 J12.B27 J12.B31 J12.B32 J12.B45 J12.B49 J12.B56 J12.B65 J12.B69 J12.B76 JP1.1 JP2.1 Q7.2(source) R35.1 R37.1 R39.1 R48.2 R49.2 R59.1 R68.2 R69.2 R76.2 R85.2 R86.2 R95.1 R103.1 R109.1 R111.2 TP16.1 U2.11(Vcc-) U3.2(V-) U4.2(VCC-) U5.3(~{EN1}) U5.6(GND) U5.9(EPAD) U6.5(2A) U6.7(3A) U6.8(GND) U7.2(GND)
V1: J3.1 Q1.1(S) Q1.2(S) Q1.3(S) Q4.5(D) Q4.6(D) Q4.7(D) Q4.8(D) R16.2 R28.1 R34.2
V2: J3.2 Q2.1(S) Q2.2(S) Q2.3(S) Q5.5(D) Q5.6(D) Q5.7(D) Q5.8(D) R17.2 R30.1 R36.2
V3: J3.3 Q3.1(S) Q3.2(S) Q3.3(S) Q6.5(D) Q6.6(D) Q6.7(D) Q6.8(D) R18.2 R32.1 R38.2
VBUS: C41.2 J12.A29 R100.2 R103.2 TP19.1
VDD: C28.1 D8.1(C) D9.1(C) D10.1(C) J1.1 J5.3 J8.3 J10.3 J12.A06 NTC1.1 R1.2 R2.2 R3.2 R6.1 R40.1 R41.1 R51.2 R96.2 R97.2 R98.2 R110.2 R112.1 U4.5(VCC+) U6.1(Vcc) U7.5(VCC)
VDD_c: C20.2 R41.2 U3.5(V+)
VDD_f: C19.2 R40.2 U2.4(Vcc+)
Buck_OUT: C34.2 C35.2 C36.2 L1.2 R91.2 R92.1 R93.2
CFBK: C29.2 R60.1 R74.1 TP12.1 U4.3(IN+)
CP_drv: C7.2 J2.1 R6.2 R7.1 R8.1 R9.1 TP4.1 U1.1(CP)
CURR_REF: J4.1 J12.B28
ENCA: J12.B16 U6.15(6Y)
ENCB: J12.B17 U6.12(5Y)
ENCZ: J12.B18 U6.10(4Y)
ETR: J12.A17 U4.1(OUT)
FB: C36.1 R93.1 R95.2 U5.4(FB)
GHS1: D1.1(C) R10.1 U1.22(GHS1)
GHS2: D2.1(C) R11.1 U1.18(GHS2)
GHS3: D3.1(C) R12.1 U1.14(GHS3)
GLS1: D4.1(C) R19.1 U1.24(GLS1)
GLS2: D5.1(C) R20.1 U1.20(GLS2)
GLS3: D6.1(C) R21.1 U1.16(GLS3)
H1: C43.1 J12.A18 R101.1
H2: C44.1 J12.A19 R102.1
H3: C45.1 J12.B19 R104.1
ID_ENABLE_n: J12.A08 U7.6(IN)
INH1: J12.A13 U1.7(INH1_IN1)
INH2: J12.A14 U1.8(INH2_IN2)
INH3: J12.A15 U1.9(INH3_IN3)
INL1: J12.B13 U1.10(INL1_EN1)
INL2: J12.B14 U1.11(INL2_EN2)
INL3: J12.B15 U1.12(INL3_EN3)
ISNS1N: J12.B21 R49.1 R54.1
ISNS1P: J12.A21 R43.2 R46.2
ISNS2N: J12.B22 R69.1 R71.1
ISNS2P: J12.A22 R60.2 R62.2 R65.2
ISNS3N: J12.B23 R86.1 R88.1
ISNS3P: J12.A23 R79.2 R83.2
LSS1: Q4.1(S) Q4.2(S) Q4.3(S) SB1.2
LSS3: Q6.1(S) Q6.2(S) Q6.3(S) SB2.2
nFAULT: LED1.1 R3.1 R117.2 R118.1 TP3.1 U1.6(nFAULT)
OPREF: C23.1 R42.1 R52.2 R57.1 R61.1 R78.1 TP10.1
OUT1: C6.1 R16.1 U1.23(OUT1)
OUT2: C9.2 R17.1 U1.19(OUT2)
OUT3: C8.2 R18.1 U1.15(OUT3)
P_GOOD: Q7.1(gate) R91.1 TP17.1 U5.2(PG)
SCREF: C5.2 J1.2 R1.1 R4.2 U1.3(SCREF)
SHUNT1N: C21.1 JP3.2 R47.2 R54.2
SHUNT1P: C21.2 R7.2 R25.2 R43.1 R44.2 SB1.1
SHUNT2N: C26.1 JP4.2 R67.2 R71.2 R75.2
SHUNT2P: C26.2 Q5.1(S) Q5.2(S) Q5.3(S) R8.2 R26.2 R62.1 R63.2 R73.2 SB1.3 SB2.1
SHUNT3N: C30.1 JP5.2 R84.2 R88.2
SHUNT3P: C30.2 R9.2 R27.2 R79.1 R80.2 SB2.3
SPI_MISO: J12.B01 U6.2(1Y)
SPI_MOSI: D9.2(A) J12.B02 R115.1
SPI_nSS: D8.2(A) J12.A01 R113.1
SPI_SCK: D10.2(A) J12.A02 R116.1
TEMP_ID: J12.A28 U7.4(D)
TPCB: C50.2 NTC1.2 R109.2 TP21.1 U7.1(S1)
VM: C3.2 C4.2 C10.2 C11.2 C12.2 C39.1(POS) C40.1(POS) J7.1 LED3.2 Q1.5(D) Q1.6(D) Q1.7(D) Q1.8(D) Q2.5(D) Q2.6(D) Q2.7(D) Q2.8(D) Q3.5(D) Q3.6(D) Q3.7(D) Q3.8(D) R90.2 R99.1 TP2.1 TP18.1 U1.4(VS)
VREF+: J12.B06 R50.2
VSNS1: C13.2 J12.A25 R29.2 R35.2 TP6.1
VSNS2: C14.2 J12.A26 R31.2 R37.2 TP7.1
VSNS3: C15.2 J12.A27 R33.2 R39.2 TP8.1
N341931: LED1.2 R2.1
N342654: R5.1 U1.2(DT_MODE)
N346164: C9.1 U1.17(BOOT2)
N346292: C6.2 U1.21(BOOT1)
N348026: R42.2 R44.1 R48.1 U2.5(IN+)
N348030: R47.1 R53.2 R56.2 U2.6(IN-)
N348034: R45.1 R53.1 R56.1 TP9.1 U2.7(OUT)
N405802: Q4.4(G) R19.2 R22.2
N420950: C33.1 D7.1 L1.1 U5.8(SW)
N423156: C37.1 C38.2 R90.1 U5.5(EN2) U5.7(VIN)
N423472: C33.2 U5.1(BOOT)
N434416: J12.B12 R118.2
N443088: J12.A12 R117.1
N444531: D4.2(A) R22.1
N444693: D5.2(A) R23.1
N444697: Q5.4(G) R20.2 R23.2
N444879: D6.2(A) R24.1
N444883: Q6.4(G) R21.2 R24.2
N445065: D3.2(A) R15.1
N445069: Q3.4(G) R12.2 R15.2
N445327: D2.2(A) R14.1
N445331: Q2.4(G) R11.2 R14.2
N445554: D1.2(A) R13.1
N445558: Q1.4(G) R10.2 R13.2
N470361: C31.2 R81.1 TP14.1 U4.4(IN-)
N471408: R73.1 R76.1 U2.10(IN+)
N471412: R75.1 R77.1 U2.9(IN-)
N471570: R74.2 R77.2 U2.8(OUT)
N472042: J4.2 R81.2
N472470: C24.1 R55.1 R59.2 U3.3(+)
N472582: R57.2 R58.2 R66.1
N478538: J6.1 R96.1 R101.2
N478542: J6.2 R97.1 R102.2
N478546: J6.3 R98.1 R104.2
N478738: C42.1 J5.2 J6.4
N479415: J9.1 R106.2
N479421: J9.2 R107.2
N479427: J9.3 R108.2
N479459: C48.1 J8.2 J9.4
N479601: J11.2 R114.2
N479607: J11.3 R115.2
N479625: J11.4 R116.2
N479657: C52.1 J10.2 J11.5
N479733: J11.1 R113.2
N480096: C51.2 R110.1 R111.1 U7.3(S2)
N487267: R28.2 R29.1
N487934: R30.2 R31.1
N488373: R32.2 R33.1
N490756: C22.2 R45.2 R46.1
N494551: R64.1 R70.1 R72.1 TP11.1 U2.1(OUT)
N494643: R61.2 R63.1 R68.1 U2.3(IN+)
N494647: R67.1 R70.2 R72.2 U2.2(IN-)
N494767: C27.2 R64.2 R65.1
N495845: R82.1 R87.1 R89.1 TP13.1 U2.14(OUT)
N495931: R78.2 R80.1 R85.1 U2.12(IN+)
N495935: R84.1 R87.2 R89.2 U2.13(IN-)
N496035: C32.2 R82.2 R83.1
N496697: R50.1 R51.1 R52.1 R55.2
N501821: R99.2 R100.1
N513408: C8.1 U1.13(BOOT3)
N519464: LED3.1 R105.2
N526328: LED2.2 R94.2
N526332: LED2.1 Q7.3(drain)
N574651: C49.2 R108.1 U6.9(4A)
N574774: C47.2 R107.1 U6.11(5A)
N574847: C46.2 R106.1 U6.14(6A)
N575649: R112.2 R114.1 U6.3(1A)
N599590: C16.2 R34.1
N599920: C17.2 R36.1
N600140: C18.2 R38.1
N605072: C25.2 R66.2 U3.4(-)
N605096: C25.1 R58.1 U3.1(OUT)

Not connected (* = marked no-connect by the designer): J12 A03* A04* A09* A10* A11* A16* A30* A33* A34* A35* A36* A37* A38* A39* A40* A41* A42* A43* A44* A46* A47* A48* A50* A51* A52* A53* A54* A55* A57* A58* A59* A60* A61* A62* A63* A64* A66* A67* A68* A70* A71* A72* A73* A74* A75* A77* A78* A79* A80* A81* A82* B03* B04* B09* B10* B11* B29* B30* B33* B34* B35* B36* B37* B38* B39* B40* B41* B42* B43* B44* B46* B47* B48* B50* B51* B52* B53* B54* B55* B57* B58* B59* B60* B61* B62* B63* B64* B66* B67* B68* B70* B71* B72* B73* B74* B75* B77* B78* B79* B80* B81* B82*; U6 4(2Y)* 6(3Y)*

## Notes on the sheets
sheet 1
- Gate Driver STDRIVE101
- STDRIVE101 VDS monitoring threshold
- REG12
- VM
- SCREF
- 0.88V
- FAULT
- nFAULT
- MODE/DT
- Open (default): Vds monitoring protection enabled
- Closed: Vds monitoring protection disabled
- STDRIVE101 comparator network
- 20A threshold
- CP
- Power and signal
  GND planes
  connection
- Closed: OC comparator protection disabled
- Open (default): OC comparator protection enabled
sheet 2
- 1
- 2
- 3
- GND
- default:
  close 1-2
  for 3-shunt
  configuration
- default:
  close 2-3
  for 3-shunt
  configuration
- PH_1
- PH_2
- PH_3
- Motor connector side
- PCI-e connector side
- Motor connector side
- PCI-e connector side
- Motor connector side
- PCI-e connector side
sheet 3
- Phase Current sensing
- Voltage reference generation
- I1
- SBR
- SBR
- SBR
- SBR
- SBR
- SBR
- OPREF
- SBR
- SBR
- 10 k
- SBR
- 100
- 100 nF
- 10 k
- TS461CLT
- I2
- SBR
- 1 nF
- SBR
- 10 k
- SBR
- Comparator for current control
- SBR
- CFBK
- I3
- SBR
- SBR
- CURR_REF_IN
- CREF
- GND
- SBR
- SBR
sheet 4
- Buck converter for 5V generation
- SBR
- SBR
- 5V
- GND_S
- PG
sheet 5
- Hall sensors connector
- Power supply connector (VM)
- Hall sensors
  supply:
  default to 5V
- VM
- VBUS
- H1
- H2
- +
- VHall
- H3
- -
- 6V-45V
- GND
- GND
- Supply connector side
- PCI-e connector side
- Quadrature Encoder connector
- Board ID and temperature sensor (NTC)
- Quadrature
  encoder supply:
  default to 5V
- TPCB
- A
- B
- Z
- VEnc
- GND
- SPI connector
- SPI Encoder supply:
  default to 5V
- MISO
- nSS
- MOSI
- SCLK
- VSPI
- GND
sheet 6
- PCI-express connector (16x)
- MC connector V2
- SPI1_SCK
- SPI1_nSS
- SPI1_MISO
- SPI1_MOSI
- SPI2_nSS
- SPI2_MISO
- SPI2_SCK
- SPI2_MOSI
- DGND
- DGND
- 5V_to_CTRLB
- 5V_to_CTRLB
- 3.3V_to_PWRB
- VREF+
- ID_ENALBLE_n
- DGND
- AGND
- DGND
- AGND
- AGND
- ADCx
- ADCx
- ADCx
- ADCx
- SBR
- ADCx
- ADCx
- SBR
- BKIN
- BKIN2
- INH1
- INL1
- INH2
- INH3
- INL2
- INL3
- DGND
- AGND
- MASTER_EN
- Encoder A+
- ETR
- Encoder B+
- Hall Sens H1
- Encoder Z
- Hall Sens H2
- Hall Sens H3
- Shunt1+
- DGND
- DGND
- Shunt1-
- Shunt2+
- Shunt2-
- Shunt3+
- Shunt3-
- AGND
- AGND
- DGND
- DGND
- Ph_Volt1+
- Ph_Volt1-
- Ph_Volt2+
- Ph_Volt2-
- Ph_Volt3+
- Temp/ID
- Curr. REF
- Ph_Volt3-
- AGND
- AGND
- VBUS
- Res. Sin
- Brake
- Res. Cos
- DGND
- DGND
- AGND
- AGND
- DGND
- AGND
